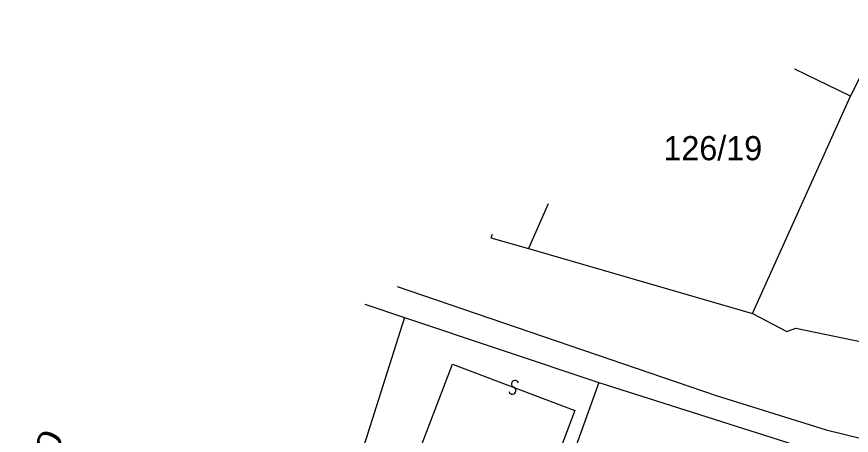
# Model space of a CAD drawing. Extents: x -680102 to -677253, y -1007548 to -1006096.
# Drawn here: x -680014.4 to -679928, y -1007092.8 to -1007049.5 of the extents above; entities that cross this region are included whole.
import ezdxf

# ---------------------------------------------------------------- set-up
doc = ezdxf.new("R2010")
doc.units = 0
for name, color, linetype, lineweight in [('1', 7, 'Continuous', 25), ('25', 7, 'Continuous', 25), ('4', 7, 'Continuous', 25)]:
    doc.layers.add(name, color=color, linetype=linetype, lineweight=lineweight)
doc.layers.add('18', color=7, linetype='Continuous')
doc.layers.add('19', color=7, linetype='Continuous')

msp = doc.modelspace()

# ---------------------------------------------------------------- linework, layer by layer
at = {"layer": '1'}
for p, q in [((-679928.04, -1007057.75), (-679933.82, -1007054.94)), ((-679959.34, -1007068.88), (-679961.39, -1007073.5)), ((-679954.1, -1007087.39), (-679962.13, -1007109.73))]:
    msp.add_line(p, q, dxfattribs=at)
for points in [[(-679965.15, -1007072.06), (-679965.26, -1007072.39), (-679961.39, -1007073.5), (-679938.19, -1007080.24), (-679928.04, -1007057.75), (-679923.88, -1007049.51)], [(-679974.97, -1007077.43), (-679941.96, -1007088.72), (-679930.57, -1007092.28), (-679915.66, -1007095.94), (-679902.15, -1007098.5), (-679887.23, -1007100.52), (-679863.69, -1007102.17), (-679845.48, -1007102.38), (-679827.03, -1007101.79), (-679807.03, -1007099.79), (-679804.33, -1007100.05), (-679799.92, -1007101.29), (-679801.05, -1007105.4), (-679801.35, -1007106.51)], [(-679978.33, -1007079.27), (-679974.23, -1007080.64), (-679954.1, -1007087.39)], [(-679938.19, -1007080.24), (-679934.64, -1007082.11), (-679933.72, -1007081.76)], [(-679974.23, -1007080.64), (-679981.15, -1007102.52), (-679962.13, -1007109.73), (-679967.03, -1007123.14)], [(-679933.72, -1007081.76), (-679927.88, -1007082.96), (-679903.06, -1007088.07)], [(-679954.1, -1007087.39), (-679930.21, -1007094.96), (-679928.84, -1007095.74)]]:
    msp.add_lwpolyline(points, dxfattribs=at)
at = {"layer": '25'}
for centre, radius, start, end in [((-679962.777, -1007087.527), 0.367, 16.39624, 248.80792), ((-679963.045, -1007088.213), 0.368, 196.56669, 68.70853)]:
    msp.add_arc(centre, radius, start, end, dxfattribs=at)
at = {"layer": '4'}
msp.add_lwpolyline([(-679969.24, -1007085.47), (-679956.58, -1007090.26), (-679961.46, -1007103.19), (-679966.21, -1007101.39), (-679966.71, -1007102.7), (-679971.2, -1007101), (-679970.71, -1007099.69), (-679974.17, -1007098.38)], close=True, dxfattribs=at)

# ---------------------------------------------------------------- texts
at = {"layer": '18'}
msp.add_text('126/19', height=2.5, dxfattribs=at).set_placement((-679947.41, -1007064.37))
at = {"layer": '19', "width": 1.25}
msp.add_text('240', height=2.5, rotation=63.901, dxfattribs=at).set_placement((-680012.421, -1007099.343))

doc.saveas('drawing.dxf')
